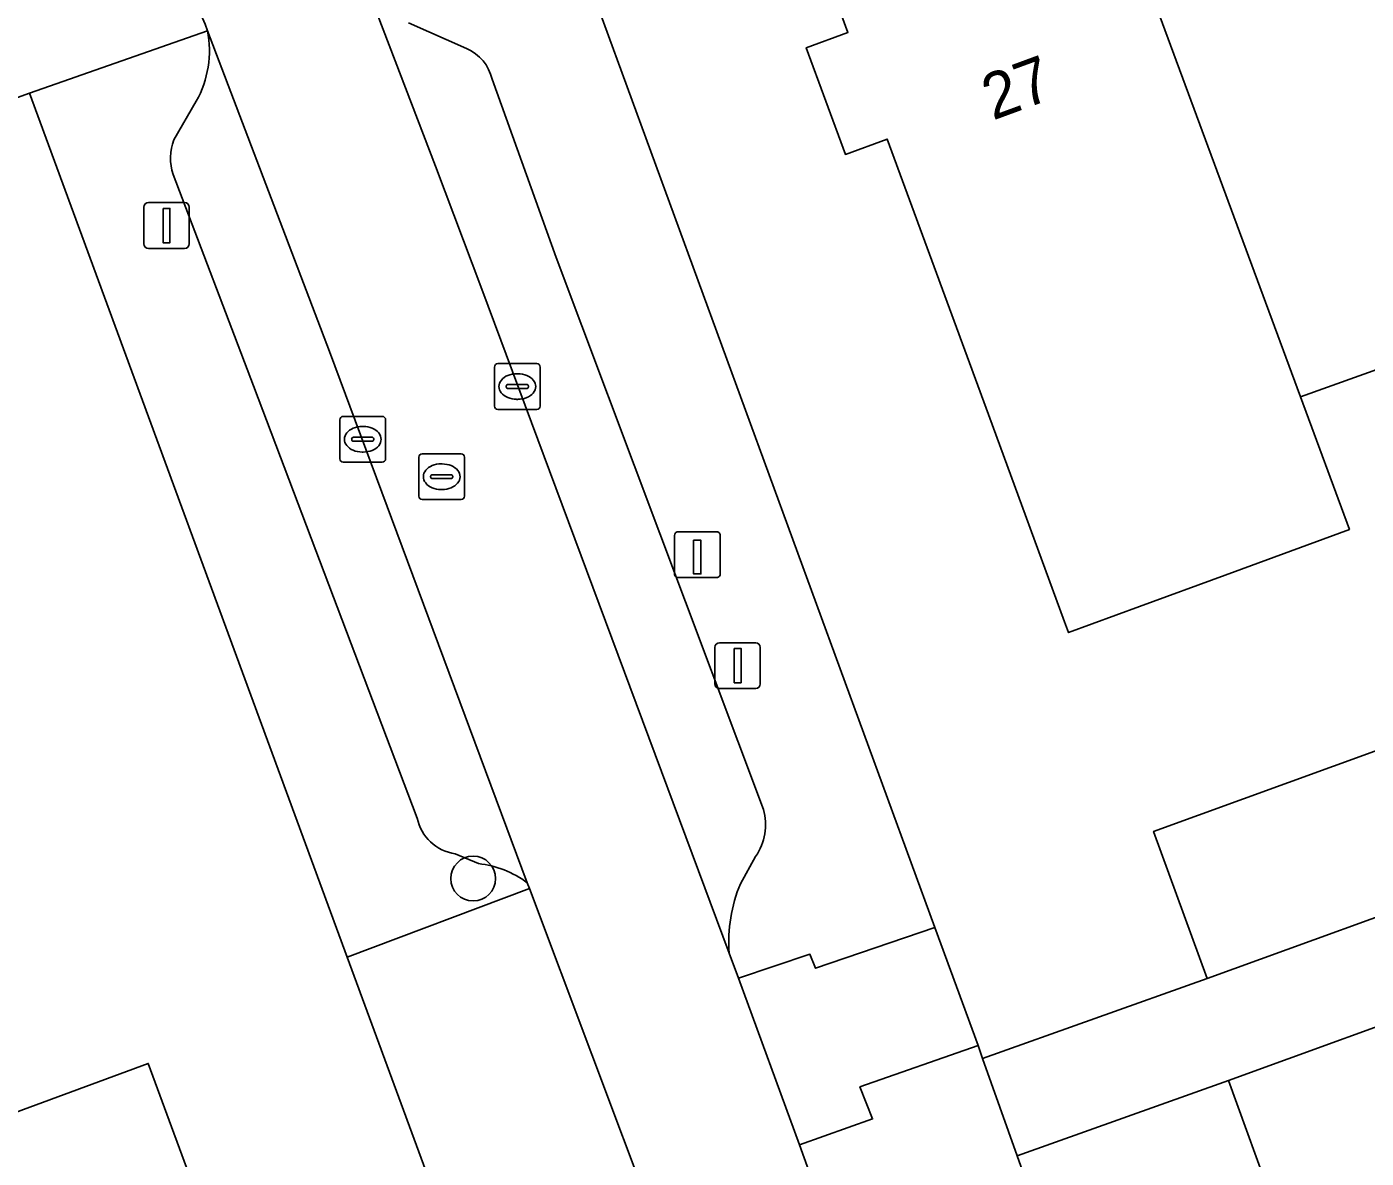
# Model space of a CAD drawing. Extents: x 161258 to 161838, y 380833 to 381727.
# Drawn here: x 161610.91 to 161640.18, y 381433.33 to 381458.06 of the extents above; entities that cross this region are included whole.
import ezdxf

# ---------------------------------------------------------------- set-up
doc = ezdxf.new("R2010")
doc.units = 0
for name, color, linetype in [('IMGEO_Boom', 7, 'Continuous'), ('IMGEO_Erf', 7, 'Continuous'), ('IMGEO_Kolk', 7, 'Continuous'), ('IMGEO_Laadpaal', 7, 'Continuous'), ('IMGEO_Lichtmast', 7, 'Continuous'), ('IMGEO_Pand', 7, 'Continuous'), ('IMGEO_Pand_nummerreeks', 7, 'Continuous'), ('IMGEO_Parkeervlak_open', 7, 'Continuous'), ('IMGEO_Rijbaan_lokaal_open', 7, 'Continuous'), ('IMGEO_Rioolput', 7, 'Continuous'), ('IMGEO_Voetpad_open', 7, 'Continuous')]:
    doc.layers.add(name, color=color, linetype=linetype)

msp = doc.modelspace()

# ---------------------------------------------------------------- linework, layer by layer
at = {"layer": 'IMGEO_Boom'}
msp.add_circle((161620.669, 381439.444), 0.489, dxfattribs=at)
at = {"layer": 'IMGEO_Erf'}
for points in [[(161692.567, 381486.83), (161622.485, 381460.994), (161630.758, 381438.372), (161631.7, 381435.792), (161631.8, 381435.51), (161636.704, 381437.258), (161635.537, 381440.474), (161641.438, 381442.614), (161644.43, 381443.699), (161645.597, 381440.484), (161648.418, 381441.597), (161650.576, 381442.391), (161665.897, 381448.031)], [(161644.57, 381452.056), (161638.75, 381449.971), (161639.816, 381447.073), (161637.103, 381446.076), (161635.232, 381445.389), (161633.679, 381444.818), (161633.593, 381445.054), (161632.008, 381449.363), (161631.512, 381450.712), (161629.712, 381455.604), (161628.803, 381455.27), (161627.947, 381457.598), (161628.856, 381457.932), (161628.725, 381458.288), (161634.845, 381460.539), (161640.663, 381462.68)], [(161625.828, 381416.218), (161620.508, 381430.682), (161617.919, 381437.722), (161610.973, 381456.609), (161591.531, 381449.546), (161590.178, 381449.054), (161586.626, 381447.764), (161584.326, 381446.929), (161582.834, 381446.387), (161582.376, 381446.221), (161568.663, 381441.239)], [(161605.743, 381432.515), (161613.568, 381435.402), (161614.764, 381432.159)], [(161638.172, 381432.274), (161637.173, 381435.03), (161632.557, 381433.385), (161638.239, 381417.444)]]:
    msp.add_lwpolyline(points, dxfattribs=at)
at = {"layer": 'IMGEO_Kolk'}
for p, q in [((161621.133, 381449.77), (161621.133, 381450.622)), ((161621.208, 381450.696), (161622.06, 381450.696)), ((161622.134, 381450.622), (161622.134, 381449.77)), ((161621.392, 381450.19), (161621.392, 381450.202)), ((161621.435, 381450.239), (161621.833, 381450.239)), ((161621.621, 381450.476), (161621.646, 381450.476)), ((161621.876, 381450.202), (161621.876, 381450.19)), ((161621.83, 381450.153), (161621.432, 381450.153)), ((161621.644, 381449.916), (161621.619, 381449.916)), ((161622.06, 381449.696), (161621.208, 381449.696)), ((161617.755, 381448.618), (161617.755, 381449.47)), ((161617.83, 381449.544), (161618.682, 381449.544)), ((161618.243, 381449.324), (161618.268, 381449.324)), ((161618.756, 381449.47), (161618.756, 381448.618)), ((161618.014, 381449.038), (161618.014, 381449.05)), ((161618.057, 381449.087), (161618.455, 381449.087)), ((161618.498, 381449.05), (161618.498, 381449.038)), ((161618.452, 381449.001), (161618.054, 381449.001)), ((161618.266, 381448.764), (161618.241, 381448.764)), ((161618.682, 381448.544), (161617.83, 381448.544))]:
    msp.add_line(p, q, dxfattribs=at)
for points in [[(161621.133, 381449.77), (161621.133, 381450.622)], [(161621.208, 381450.696), (161622.06, 381450.696)], [(161622.134, 381450.622), (161622.134, 381449.77)], [(161622.06, 381449.696), (161621.208, 381449.696)], [(161617.755, 381448.618), (161617.755, 381449.47)], [(161617.83, 381449.544), (161618.682, 381449.544)], [(161618.756, 381449.47), (161618.756, 381448.618)], [(161618.682, 381448.544), (161617.83, 381448.544)]]:
    msp.add_lwpolyline(points, dxfattribs=at)
for centre, radius, start, end in [((161621.21, 381450.62), 0.0765, 91.552, 178.448), ((161621.21, 381450.62), 0.0765, 91.552, 178.448), ((161622.058, 381450.62), 0.0765, 1.552, 88.448), ((161622.058, 381450.62), 0.0765, 1.552, 88.448), ((161621.432, 381450.199), 0.0403, 85.8775, 175.7526), ((161621.429, 381450.189), 0.0366, 178.938, 274.7102), ((161621.833, 381450.196), 0.043, 264.8664, 352.4533), ((161621.837, 381450.201), 0.0386, 1.7309, 96.639), ((161621.21, 381449.772), 0.0765, 181.552, 268.448), ((161621.21, 381449.772), 0.0765, 181.552, 268.448), ((161622.058, 381449.772), 0.0765, 271.552, 358.448), ((161622.058, 381449.772), 0.0765, 271.552, 358.448), ((161617.832, 381449.468), 0.0765, 91.552, 178.448), ((161617.832, 381449.468), 0.0765, 91.552, 178.448), ((161618.68, 381449.468), 0.0765, 1.552, 88.448), ((161618.68, 381449.468), 0.0765, 1.552, 88.448), ((161618.054, 381449.047), 0.0403, 85.8775, 175.7526), ((161618.051, 381449.037), 0.0366, 178.938, 274.7102), ((161618.455, 381449.044), 0.043, 264.8664, 352.4533), ((161618.459, 381449.049), 0.0386, 1.7309, 96.639), ((161617.832, 381448.62), 0.0765, 181.552, 268.448), ((161617.832, 381448.62), 0.0765, 181.552, 268.448), ((161618.68, 381448.62), 0.0765, 271.552, 358.448), ((161618.68, 381448.62), 0.0765, 271.552, 358.448)]:
    msp.add_arc(centre, radius, start, end, dxfattribs=at)
for centre, major_axis, ratio, start_param, end_param in [((161621.62, 381450.196), (-0.387, 0.002), 0.722429, 4.712389, 7.853982), ((161621.645, 381450.196), (-0.39, 0.002), 0.717154, 1.570796, 4.712389), ((161618.242, 381449.044), (-0.387, 0.002), 0.722429, 4.712389, 7.853982), ((161618.267, 381449.044), (-0.39, 0.002), 0.717154, 1.570796, 4.712389)]:
    msp.add_ellipse(centre, major_axis=major_axis, ratio=ratio, start_param=start_param, end_param=end_param, dxfattribs=at)
at = {"layer": 'IMGEO_Laadpaal'}
for p, q in [((161625.985, 381447.022), (161625.144, 381447.022)), ((161625.985, 381447.022), (161625.144, 381447.022)), ((161625.069, 381446.938), (161625.069, 381446.097)), ((161625.069, 381446.938), (161625.069, 381446.097)), ((161626.069, 381446.106), (161626.069, 381446.947)), ((161626.069, 381446.106), (161626.069, 381446.947)), ((161625.153, 381446.022), (161625.994, 381446.022)), ((161625.153, 381446.022), (161625.994, 381446.022))]:
    msp.add_line(p, q, dxfattribs=at)
msp.add_lwpolyline([(161625.484, 381446.835), (161625.644, 381446.835), (161625.644, 381446.102), (161625.484, 381446.102), (161625.484, 381446.835)], dxfattribs=at)
for centre, start, end in [((161625.147, 381446.944), 92.4484, 184.2845), ((161625.147, 381446.944), 92.4484, 184.2845), ((161625.991, 381446.944), 2.4484, 94.2845), ((161625.991, 381446.944), 2.4484, 94.2845), ((161625.147, 381446.1), 182.4484, 274.2845), ((161625.147, 381446.1), 182.4484, 274.2845), ((161625.991, 381446.1), 272.4484, 4.2845), ((161625.991, 381446.1), 272.4484, 4.2845)]:
    msp.add_arc(centre, 0.0779, start, end, dxfattribs=at)
at = {"layer": 'IMGEO_Lichtmast'}
for p, q in [((161613.474, 381453.315), (161613.474, 381454.115)), ((161613.474, 381454.115), (161613.474, 381453.315)), ((161613.574, 381454.215), (161614.364, 381454.215)), ((161614.364, 381454.215), (161613.574, 381454.215)), ((161614.464, 381454.115), (161614.464, 381453.315)), ((161614.464, 381453.315), (161614.464, 381454.115)), ((161614.364, 381453.215), (161613.574, 381453.215)), ((161613.574, 381453.215), (161614.364, 381453.215)), ((161625.952, 381443.696), (161625.952, 381444.496)), ((161625.952, 381444.496), (161625.952, 381443.696)), ((161626.052, 381444.596), (161626.842, 381444.596)), ((161626.842, 381444.596), (161626.052, 381444.596)), ((161626.942, 381444.496), (161626.942, 381443.696)), ((161626.942, 381443.696), (161626.942, 381444.496)), ((161626.842, 381443.596), (161626.052, 381443.596)), ((161626.052, 381443.596), (161626.842, 381443.596))]:
    msp.add_line(p, q, dxfattribs=at)
for points in [[(161613.894, 381454.09), (161614.044, 381454.09), (161614.044, 381453.34), (161613.894, 381453.34), (161613.894, 381454.09)], [(161626.372, 381444.471), (161626.522, 381444.471), (161626.522, 381443.721), (161626.372, 381443.721), (161626.372, 381444.471)]]:
    msp.add_lwpolyline(points, dxfattribs=at)
for centre, start, end in [((161613.574, 381454.115), 90, 180), ((161613.574, 381454.115), 90, 180), ((161614.364, 381454.115), 0, 90), ((161614.364, 381454.115), 360, 90), ((161613.574, 381453.315), 180, 270), ((161613.574, 381453.315), 180, 270), ((161614.364, 381453.315), 270, 0), ((161614.364, 381453.315), 270, 0), ((161626.052, 381444.496), 90, 180), ((161626.052, 381444.496), 90, 180), ((161626.842, 381444.496), 0, 90), ((161626.842, 381444.496), 360, 90), ((161626.052, 381443.696), 180, 270), ((161626.052, 381443.696), 180, 270), ((161626.842, 381443.696), 270, 0), ((161626.842, 381443.696), 270, 0)]:
    msp.add_arc(centre, 0.1, start, end, dxfattribs=at)
at = {"layer": 'IMGEO_Pand'}
for points in [[(161634.845, 381460.539), (161638.75, 381449.971), (161644.57, 381452.056), (161640.663, 381462.68)], [(161634.845, 381460.539), (161628.725, 381458.288), (161628.856, 381457.932), (161627.947, 381457.598), (161628.803, 381455.27), (161629.712, 381455.604), (161631.512, 381450.712), (161632.008, 381449.363), (161633.593, 381445.054), (161633.679, 381444.818), (161635.232, 381445.389), (161637.103, 381446.076), (161639.816, 381447.073), (161638.75, 381449.971)], [(161642.618, 381439.403), (161641.438, 381442.614), (161635.537, 381440.474), (161636.704, 381437.258)], [(161647.334, 381439.729), (161641.987, 381437.79), (161642.312, 381436.894), (161637.173, 381435.03), (161638.172, 381432.274), (161637.794, 381432.137), (161638.703, 381429.63), (161639.085, 381429.769), (161639.267, 381429.267), (161650.5, 381433.278), (161650.475, 381433.348), (161651.868, 381433.855), (161650.549, 381437.497), (161648.421, 381436.726)], [(161605.743, 381432.515), (161606.966, 381429.283), (161614.764, 381432.159), (161613.568, 381435.402)]]:
    msp.add_lwpolyline(points, close=True, dxfattribs=at)
at = {"layer": 'IMGEO_Parkeervlak_open'}
for points in [[(161618.312, 381459.03), (161619.845, 381455.009), (161620.858, 381452.321), (161626.262, 381437.814)], [(161620.526, 381457.581), (161619.253, 381458.145)], [(161617.533, 381450.961), (161614.862, 381457.971)], [(161622.485, 381453.014), (161621.083, 381456.914)], [(161614.619, 381456.43), (161614.131, 381455.588)], [(161614.115, 381454.833), (161615.87, 381450.209), (161619.445, 381440.765)], [(161627.01, 381440.954), (161622.485, 381453.014)], [(161621.851, 381439.353), (161617.533, 381450.961)], [(161620.279, 381439.987), (161620.786, 381439.77)], [(161626.509, 381439.331), (161626.841, 381439.926)]]:
    msp.add_lwpolyline(points, dxfattribs=at)
for centre, radius, start, end in [((161612.633, 381457.533), 2.272, 330.9599, 11.1177), ((161620.152, 381456.703), 0.954, 12.7837, 66.9457), ((161615.125, 381455.189), 1.071, 158.1398, 199.4321), ((161625.86, 381440.615), 1.199, 324.922, 16.4066), ((161620.41, 381440.963), 0.985, 191.6186, 262.3606), ((161620.52, 381437.523), 2.263, 53.9799, 83.2545), ((161629.628, 381438.045), 3.374, 157.5852, 183.9192)]:
    msp.add_arc(centre, radius, start, end, dxfattribs=at)
at = {"layer": 'IMGEO_Rijbaan_lokaal_open'}
for points in [[(161633.562, 381417.932), (161631.642, 381423.104), (161628.071, 381432.908), (161628.007, 381433.055), (161627.799, 381433.622), (161626.464, 381437.265), (161626.262, 381437.814), (161620.858, 381452.321), (161619.845, 381455.009), (161618.312, 381459.03)], [(161614.862, 381457.971), (161617.533, 381450.961), (161621.851, 381439.353), (161621.897, 381439.229), (161624.621, 381431.971), (161629.58, 381418.332)]]:
    msp.add_lwpolyline(points, dxfattribs=at)
msp.add_arc((161612.014, 381457.048), 2.994, 17.9573, 108.2607, dxfattribs=at)
at = {"layer": 'IMGEO_Rioolput'}
for p, q in [((161619.555, 381448.726), (161620.407, 381448.726)), ((161619.48, 381447.8), (161619.48, 381448.652)), ((161619.968, 381448.506), (161619.993, 381448.506)), ((161620.481, 381448.652), (161620.481, 381447.8)), ((161619.739, 381448.22), (161619.739, 381448.232)), ((161620.177, 381448.183), (161619.779, 381448.183)), ((161619.782, 381448.269), (161620.18, 381448.269)), ((161620.223, 381448.232), (161620.223, 381448.22)), ((161619.991, 381447.946), (161619.966, 381447.946)), ((161620.407, 381447.726), (161619.555, 381447.726))]:
    msp.add_line(p, q, dxfattribs=at)
for points in [[(161619.555, 381448.726), (161620.407, 381448.726)], [(161619.48, 381447.8), (161619.48, 381448.652)], [(161620.481, 381448.652), (161620.481, 381447.8)], [(161620.407, 381447.726), (161619.555, 381447.726)]]:
    msp.add_lwpolyline(points, dxfattribs=at)
for centre, radius, start, end in [((161619.557, 381448.65), 0.0765, 91.552, 178.448), ((161619.557, 381448.65), 0.0765, 91.552, 178.448), ((161620.405, 381448.65), 0.0765, 1.552, 88.448), ((161620.405, 381448.65), 0.0765, 1.552, 88.448), ((161619.779, 381448.229), 0.0403, 85.8775, 175.7526), ((161619.776, 381448.219), 0.0366, 178.938, 274.7102), ((161620.18, 381448.226), 0.043, 264.8664, 352.4533), ((161620.184, 381448.231), 0.0386, 1.7309, 96.639), ((161619.557, 381447.802), 0.0765, 181.552, 268.448), ((161619.557, 381447.802), 0.0765, 181.552, 268.448), ((161620.405, 381447.802), 0.0765, 271.552, 358.448), ((161620.405, 381447.802), 0.0765, 271.552, 358.448)]:
    msp.add_arc(centre, radius, start, end, dxfattribs=at)
for centre, major_axis, ratio, start_param, end_param in [((161619.967, 381448.226), (-0.387, 0.002), 0.722429, 4.712389, 7.853982), ((161619.992, 381448.226), (-0.39, 0.002), 0.717154, 1.570796, 4.712389)]:
    msp.add_ellipse(centre, major_axis=major_axis, ratio=ratio, start_param=start_param, end_param=end_param, dxfattribs=at)
at = {"layer": 'IMGEO_Voetpad_open'}
for points in [[(161626.262, 381437.814), (161626.464, 381437.265), (161628.026, 381437.789), (161628.152, 381437.484), (161630.758, 381438.372), (161622.485, 381460.994)], [(161611.076, 381459.891), (161605.602, 381457.905), (161590.467, 381452.331), (161589.036, 381451.805), (161590.178, 381449.054), (161591.531, 381449.546), (161610.973, 381456.609), (161614.862, 381457.971)], [(161619.253, 381458.145), (161620.526, 381457.581)], [(161614.862, 381457.971), (161610.973, 381456.609), (161617.919, 381437.722), (161621.897, 381439.229), (161621.851, 381439.353)], [(161621.083, 381456.914), (161622.485, 381453.014), (161627.01, 381440.954)], [(161614.131, 381455.588), (161614.619, 381456.43)], [(161615.87, 381450.209), (161614.115, 381454.833)], [(161619.445, 381440.765), (161615.87, 381450.209)], [(161665.897, 381448.031), (161650.576, 381442.391), (161648.418, 381441.597), (161645.597, 381440.484), (161642.618, 381439.403), (161636.704, 381437.258), (161631.8, 381435.51), (161632.557, 381433.385), (161637.173, 381435.03), (161642.312, 381436.894), (161641.987, 381437.79), (161647.334, 381439.729), (161666.191, 381446.595)], [(161620.786, 381439.77), (161620.279, 381439.987)], [(161626.841, 381439.926), (161626.509, 381439.331)], [(161637.547, 381412.742), (161638.239, 381417.444), (161632.557, 381433.385), (161631.8, 381435.51), (161631.7, 381435.792), (161629.12, 381434.891), (161629.396, 381434.192), (161627.799, 381433.622), (161628.007, 381433.055), (161628.071, 381432.908)]]:
    msp.add_lwpolyline(points, dxfattribs=at)
for points in [[(161621.897, 381439.229), (161617.919, 381437.722), (161620.508, 381430.682), (161622.544, 381431.448), (161622.657, 381431.22), (161624.621, 381431.971)], [(161630.758, 381438.372), (161628.152, 381437.484), (161628.026, 381437.789), (161626.464, 381437.265), (161627.799, 381433.622), (161629.396, 381434.192), (161629.12, 381434.891), (161631.7, 381435.792)]]:
    msp.add_lwpolyline(points, close=True, dxfattribs=at)
for centre, radius, start, end in [((161612.014, 381457.048), 2.994, 17.9573, 108.2607), ((161612.633, 381457.533), 2.272, 330.9599, 11.1177), ((161620.152, 381456.703), 0.954, 12.7837, 66.9457), ((161615.125, 381455.189), 1.071, 158.1398, 199.4321), ((161625.86, 381440.615), 1.199, 324.922, 16.4066), ((161620.41, 381440.963), 0.985, 191.6186, 262.3606), ((161620.52, 381437.523), 2.263, 53.9799, 83.2545), ((161629.628, 381438.045), 3.374, 157.5852, 183.9192)]:
    msp.add_arc(centre, radius, start, end, dxfattribs=at)

# ---------------------------------------------------------------- texts
at = {"layer": 'IMGEO_Pand_nummerreeks'}
msp.add_text('27', height=1, rotation=20.1968, dxfattribs=at).set_placement((161632.023, 381456.006))

doc.saveas('drawing.dxf')
